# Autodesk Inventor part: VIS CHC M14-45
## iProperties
Created: 2004-11
Part Number: VIS CHC M14-45
Document SubType Name: Modeling
Designer: Bruno
Manufacturer: Standard
Standards Organization: Custom
Author: Bruno
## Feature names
1. Base1
